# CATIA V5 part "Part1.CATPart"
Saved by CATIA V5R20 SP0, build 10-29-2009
Part number: Part1
Material "Orange"
Material "Stone wall"
Material "Toon"
Material "Aluminium brushed"
Material "Toon"
Material "Satin light red": density 7190 kg/m3, Young's modulus 7e+10 Pa, Poisson ratio 0.3, thermal expansion 6.2e-06 1/K
Bounding box of the stored display mesh (mm): x -357.963 to 357.963, y -357.963 to 357.963, z -36 to 695.353
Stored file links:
  D:\liandongzhou\Part1.CATPart
  D:\catiaM\win_b64\startup\materials\Advanced_Materials.CATMaterial
  D:\catiaM\win_b64\startup\materials\shaders\CATIA_Toon.cgfx
  D:\catiaM\win_b64\startup\materials\shaders\CATIA_Diffuse_2DMap_StoneWall_256.dds
  D:\catiaM\win_b64\startup\materials\shaders\CATIA_Normal_2DMap_StoneWall_512.dds
  D:\catiaM\win_b64\startup\materials\shaders\CATIA_Leather.cgfx
  D:\catiaM\win_b64\startup\materials\shaders\CATIA_Environment_CUBEMap_Street_1024.dds
  D:\catiaM\win_b64\startup\materials\shaders\CATIA_Normal_2DMap_Flake_1024.dds
  D:\catiaM\win_b64\startup\materials\shaders\CATIA_CarPaint_Polished.cgfx
  D:\catiaM\win_b64\startup\materials\shaders\CATIA_Environment_2DMap_Street_2048.dds
  D:\catiaM\win_b64\startup\materials\shaders\CATIA_Normal_2DMap_Scratches_1024.dds
  D:\catiaM\win_b64\startup\materials\shaders\CATIA_Metal_Brushed.cgfx
  D:\catiaM\win_b64\startup\materials\shaders\CATIA_Diffuse_2DMap_WoodCedar_512.dds
  D:\catiaM\win_b64\startup\materials\shaders\CATIA_Environment_CUBEMap_Hall_1024.dds
  D:\catiaM\win_b64\startup\materials\shaders\CATIA_Wood_Polished.cgfx
  D:\catiaM\win_b64\startup\materials\textures\wire_netting.png
  D:\catiaM\win_b64\startup\materials\environment_map\CATIA_Environment_2DMap_Chroma1_256.jpg
  D:\catiaM\win_b64\startup\materials\environment_map\CATIA_Environment_2DMap_LightRedSatin_256.jpg
  D:\catiaM\win_b64\startup\materials\textures\hex_grid.png
  D:\catiaM\win_b64\startup\materials\environment_map\CATIA_Environment_2DMap_Garden_256.jpg
  D:\liandongzhou\V.CATPart
  D:\catiaM\win_b64\startup\materials\environment_map\CATIA_Environment_2DMap_Chroma2_256.jpg
  D:\catiaM\win_b64\startup\materials\environment_map\CATIA_Environment_2DMap_DarkRedSatin_256.jpg
  D:\catiaM\win_b64\startup\materials\shaders\CATIA_Normal_2DMap_GridPlate_1024.dds
  D:\catiaM\win_b64\startup\materials\shaders\CATIA_Environment_2DMap_Hall_2048.dds
  D:\catiaM\win_b64\startup\materials\shaders\CATIA_Normal_2DMap_MZDotGrid_1024.dds
  D:\catiaM\win_b64\startup\materials\shaders\CATIA_Opacity_2DMap_MZDotGrid_1024.dds
  D:\catiaM\win_b64\startup\materials\shaders\CATIA_Metal_Grid.cgfx
  D:\catiaM\win_b64\startup\materials\environment_map\CATIA_Environment_2DMap_Satin_256.jpg
  D:\catiaM\win_b64\startup\materials\textures\dot_grid.png
  D:\catiaM\win_b64\startup\materials\textures\dot_grid2.png
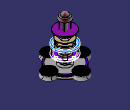
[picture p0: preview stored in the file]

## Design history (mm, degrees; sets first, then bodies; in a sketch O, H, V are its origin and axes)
Set1
  Plane1: type Offset, RefPlane xy-plane, Offset 10
  Set2
    Plane2: type Offset, RefPlane xy-plane, Offset 20 {= Plane1.Offset * 2}
    Plane3: type Offset, RefPlane xy-plane, Offset 30 {= Plane1.Offset * 3}
    Plane4: type Offset, RefPlane xy-plane, Offset 40 {= Plane1.Offset * 4}
    Plane5: type Offset, RefPlane xy-plane, Offset 50 {= Plane1.Offset * 5}
    Plane6: type Offset, RefPlane xy-plane, Offset 60 {= Plane1.Offset * 6}
    Plane7: type Offset, RefPlane xy-plane, Offset 70 {= Plane1.Offset * 7}
    Plane8: type Offset, RefPlane xy-plane, Offset 80 {= Plane1.Offset * 8}
    Plane9: type Offset, RefPlane xy-plane, Offset 90 {= Plane1.Offset * 9}
    Plane10: type Offset, RefPlane xy-plane, Offset 100 {= Plane1.Offset * 10}
    Plane11: type Offset, RefPlane xy-plane, Offset 110 {= Plane1.Offset * 11}
    Plane12: type Offset, RefPlane xy-plane, Offset 120 {= Plane1.Offset * 12}
    Plane13: type Offset, RefPlane xy-plane, Offset 130 {= Plane1.Offset * 13}
    Plane14: type Offset, RefPlane xy-plane, Offset 140 {= Plane1.Offset * 14}
    Plane15: type Offset, RefPlane xy-plane, Offset 150 {= Plane1.Offset * 15}
    Plane16: type Offset, RefPlane xy-plane, Offset 160 {= Plane1.Offset * 16}
    Plane17: type Offset, RefPlane xy-plane, Offset 170 {= Plane1.Offset * 17}
    Plane18: type Offset, RefPlane xy-plane, Offset 180 {= Plane1.Offset * 18}
    Plane19: type Offset, RefPlane xy-plane, Offset 190 {= Plane1.Offset * 19}
    Plane20: type Offset, RefPlane xy-plane, Offset 200 {= Plane1.Offset * 20}
    Plane21: type Offset, RefPlane xy-plane, Offset 210 {= Plane1.Offset * 21}
    Plane22: type Offset, RefPlane xy-plane, Offset 220 {= Plane1.Offset * 22}
    Plane23: type Offset, RefPlane xy-plane, Offset 230 {= Plane1.Offset * 23}
    Plane24: type Offset, RefPlane xy-plane, Offset 240 {= Plane1.Offset * 24}
    Plane25: type Offset, RefPlane xy-plane, Offset 250 {= Plane1.Offset * 25}
    Plane26: type Offset, RefPlane xy-plane, Offset 260 {= Plane1.Offset * 26}
  Plane27: type Offset, RefPlane xy-plane, Offset 30, reversed
  Sketch1 on Plane27, origin (0, 0, -30), H (1, 0, 0), V (0, 1, 0)
    circle A1 centre (0, 0) radius 250
    radius A1 = 250
    radius A1 = 250 (reference)
Body1 (main body), material "Stone wall"
  Pad1: profile Sketch1, direction (0, 0, -1), length 6
  Sketch2 on xy-plane, origin (0, 0, 0), H (1, 0, 0), V (0, 1, 0)
    circle A1 centre (0, 0) radius 250
    radius A1 = 250
  Pad2: profile Sketch2, direction (0, 0, 1), length 10
  Sketch3 on end face of Pad1, origin (0, 0, -36), H (1, 0, 0), V (0, -1, 0)
    point P1 (125, 0)
    reference projected circle E1 centre (0, 0) radius 250 from Sketch2.A1
    point P2 (250, 0)
    circle A1 centre (250, 0) radius 100
    circle A2 centre (250, 0) radius 110
    distance P1 O = 125
    radius E1 = 250 (reference)
    radius A1 = 100
    distance V P2 = 250
    radius A2 = 110
    coincidence: P1 H, P2 H
  Line1: type PtDir, RefPoint Sketch3.P1, Direction (0, 0, 1), Start 0, End 20
  Plane28: type Normal, Curve Line1, RefPoint Sketch3.P1
  Plane29: type Offset, RefPlane Plane28, Offset 5
  Set3
    Plane30: type Offset, RefPlane Plane28, Offset 10 {= Plane29.Offset * 2}
    Plane31: type Offset, RefPlane Plane28, Offset 15 {= Plane29.Offset * 3}
    Plane32: type Offset, RefPlane Plane28, Offset 20 {= Plane29.Offset * 4}
    Plane33: type Offset, RefPlane Plane28, Offset 25 {= Plane29.Offset * 5}
    Plane34: type Offset, RefPlane Plane28, Offset 30 {= Plane29.Offset * 6}
    Plane35: type Offset, RefPlane Plane28, Offset 35 {= Plane29.Offset * 7}
    Plane36: type Offset, RefPlane Plane28, Offset 40 {= Plane29.Offset * 8}
    Plane37: type Offset, RefPlane Plane28, Offset 45 {= Plane29.Offset * 9}
    Plane38: type Offset, RefPlane Plane28, Offset 50 {= Plane29.Offset * 10}
    Plane39: type Offset, RefPlane Plane28, Offset 55 {= Plane29.Offset * 11}
  Sketch4 on Plane31, origin (0, 0, -21), H (1, 0, 0), V (0, 1, 0)
    circle A1 centre (125, 0) radius 2.8352
    point P1 (125, 0)
    point P2 (127.8352, 0)
    distance P1 V = 125
    coincidence: P1 H, A1 P2, P2 H
  Sketch5 on Plane35, origin (0, 0, -1), H (1, 0, 0), V (0, 1, 0)
    point P1 (125, 0)
    circle A1 centre (250, 0) radius 83
    point P2 (250, 0)
    distance V P2 = 250
    radius A1 = 83
    coincidence: P2 H
  Sketch6 on Plane36, origin (0, 0, 4), H (1, 0, 0), V (0, 1, 0)
    point P1 (125, 0)
    circle A1 centre (250, 0) radius 88
    point P2 (250, 0)
    radius A1 = 88
    distance V P2 = 250
    coincidence: P2 H
  Sketch7 on Plane37, origin (0, 0, 9), H (1, 0, 0), V (0, 1, 0)
    point P1 (125, 0)
    circle A1 centre (249.5227, 0) radius 93
    point P2 (249.5227, 0)
    distance P1 H = 0
    radius A1 = 93
    coincidence: P2 H
  Sketch8 on Plane38, origin (0, 0, 14), H (1, 0, 0), V (0, 1, 0)
    point P1 (125, 0)
    circle A1 centre (250, 0) radius 98
    reference projected circle E1 centre (0, 0) radius 250 from Sketch2.A1
    distance P1 H = 0
    distance P1 V = 125
    radius A1 = 98
    radius E1 = 250 (reference)
  Sketch9 on Plane39, origin (0, 0, 19), H (1, 0, 0), V (0, 1, 0)
    point P1 (125, 0)
    circle A1 centre (250, 0) radius 106.5
    point P2 (250, 0)
    distance P1 H = 0
    distance P1 V = 125
    radius A1 = 106.5
    coincidence: P2 H
  Plane40: type Offset, RefPlane Plane39, Offset 5
  Set4
    Plane41: type Offset, RefPlane Plane39, Offset 10 {= Plane40.Offset * 2}
    Plane42: type Offset, RefPlane Plane39, Offset 15 {= Plane40.Offset * 3}
    Plane43: type Offset, RefPlane Plane39, Offset 20 {= Plane40.Offset * 4}
  Sketch10 on xy-plane, origin (0, 0, 0), H (1, 0, 0), V (0, 1, 0)
    circle A1 centre (0, 0) radius 40
    point P1 (0, 0)
    distance P1 H = 0
    distance P1 V = 0
    radius A1 = 40
  Sketch11 on Plane27, origin (0, 0, -30), H (1, 0, 0), V (0, 1, 0)
    circle A1 centre (0, 0) radius 40
    point P1 (0, 0)
    distance P1 H = 0
    distance P1 V = 0
    radius A1 = 40
  Body2 "底座凹槽"
    Loft1: solid, Sections (Sketch11; Sketch10)
  Trim1: tool Body2
  Sketch12 on Plane2, origin (0, 0, 20), H (1, 0, 0), V (0, 1, 0)
    circle A1 centre (0, 0) radius 70
    radius A1 = 70
  Pad3 "紫二层": profile Sketch12, direction (0, 0, 1), length 17, mirrored extent
  Sketch13 on start face of Pad3, origin (0, 0, 3), H (1, 0, 0), V (0, -1, 0)
    circle A1 centre (0, 0) radius 70
    arc A2 centre (48.9898, -50) radius 12 from (39.7301, -57.6326) to (56.8098, -40.898) ccw
    point P1 (48.9898, -50)
    arc A3 centre (-48.9898, 50) radius 12 from (-39.7301, 57.6326) to (-56.8098, 40.898) ccw
    point P2 (-48.9898, 50)
    construction line L1 (48.9898, -50) -> (30, -70)
    construction line L2 (48.9898, -50) -> (80, -19.6163)
    point P5 (56.8098, -40.898)
    point P6 (39.7301, -57.6326)
    axis line L3 (-30, 70) -> (-68.0952, 30)
    point P9 (-56.8098, 40.898)
    point P10 (-39.7301, 57.6326)
    radius A1 = 70
    radius A3 = 12
    radius A2 = 12
    coincidence: P1 A1, P2 A1, A1 P5, A1 P6, A1 P9, A1 P10
    tangency: L2 A1, L3 A1
  Body3 "pulley"
    Sketch14 on Plane44, origin (0, 0, 0), H (0, 1, 0), V (0, 0, 1)
      construction line L1 (0, 33) -> (180, 33)
      reference projected line E1 (-70, 37) -> (70, 37) from edge [face of Pad3 from Sketch12.A1 | end face of Pad3]
      distance L1 E1 = 4
      horizontal: L1 H
    Sketch15 on Plane44, origin (0, 0, 0), H (0, 1, 0), V (0, 0, 1)
      construction line L1 (0, 21) -> (180, 21)
      point P1 (0, 21)
      construction line L2 (65.5, 50) -> (65.5, -20)
      construction line L3 (40.5, 40) -> (40.5, -30)
      construction line L4 (0, 36) -> (78.6177, 36)
      point P7 (0, 36)
      construction line L5 (0, 18) -> (84.1873, 18)
      point P9 (0, 18)
      reference projected line E1 (-70, 3) -> (70, 3) from edge [start face of Pad3 | face of Pad3 from Sketch12.A1]
      construction line L6 (-159.9768, 21) -> (244.4965, 36)
      point P11 (-159.9768, 21)
      point P12 (244.4965, 36)
      construction line L7 (-159.9768, 21) -> (-123.6891, 18)
      point P13 (-123.6891, 18)
      line L8 (40.5, 28.4347) -> (40.5, 4.4261)
      point P14 (40.5, 28.4347)
      point P15 (40.5, 4.4261)
      line L9 (40.5, 28.4347) -> (96.2575, 30.5025)
      line L10 (40.5, 4.4261) -> (96.2575, -0.1835)
      line L11 (96.2575, 30.5025) -> (96.2575, -0.1835)
      distance L2 V = 65.5
      distance L3 L2 = 25
      distance L4 L1 = 15
      distance L5 E1 = 15
      angle L6 L7 = 6.8499
      coincidence: P1 V, P7 V, P9 V, P11 L1, P12 L4, P13 L5, P14 L6, P14 L3, P15 L7
      horizontal: L1 H, L4 H, L5 H
      vertical: L2 V, L3 V, L8 V, L11 V
      parallelism: L9 L6, L10 L7
    Shaft1: profile Sketch15, axis Sketch15.V, angle 360
  Remove1: tool Body3
Body4
  Line2: type PtDir, RefPoint Sketch12.O, Direction (0, 0, 1), Start 0, End 20
  Plane44: type 2Lines, Element1 Sketch12.V, Element2 Line2
Body5, material "Orange"
  Sketch16 on Plane5, origin (0, 0, 50), H (1, 0, 0), V (0, 1, 0)
    circle A1 centre (0, 0) radius 32.861
  Pad4: profile Sketch16, direction (0, 0, -1), length 30
Body6, material "Toon"
  Sketch17 on Plane5, origin (0, 0, 50), H (1, 0, 0), V (0, 1, 0)
    circle A1 centre (0, 0) radius 70.6625
  Pad5: profile Sketch17, direction (0, 0, 1), length 6
  Sketch18 on Plane7, origin (0, 0, 70), H (1, 0, 0), V (0, 1, 0)
    circle A1 centre (0, 0) radius 79.2104
  Pad6: profile Sketch18, direction (0, 0, -1), length 4
  Fillet1: radius 4, on edge [end face of Pad6 | face of Pad6 from Sketch18.A1]
  Sketch19 on end face of Pad5, origin (0, 0, 56), H (1, 0, 0), V (0, 1, 0)
    circle A1 centre (0, 0) radius 28.2843
  Pad7: profile Sketch19, direction (0, 0, 1), length 12
  Fillet2: radius 3, on edge [face of Pad5 from Sketch17.A1 | end face of Pad5]; edge [start face of Pad5 | face of Pad5 from Sketch17.A1]
  Sketch20 on start face of Pad6, origin (0, 0, 70), H (1, 0, 0), V (0, 1, 0)
    arc A1 centre (0, 0) radius 63.2456 from (-20, 60) to (-60.2299, 19.2965) ccw
    arc A2 centre (0, 0) radius 30 from (-10, 28.2843) to (-27.0282, 13.0183) ccw
    line L1 (-20, 60) -> (-10, 28.2843)
    line L2 (10, 28.2843) -> (20, 60)
    line L3 (-27.0282, 13.0183) -> (-60.2299, 19.2965)
    line L4 (-27.0282, -13.0183) -> (-59.658, -20.9982)
    point P7 (-27.0282, -13.0183)
    line L5 (-12.7179, -27.1709) -> (-21.2168, -59.5806)
    point P8 (-12.7179, -27.1709)
    point P9 (-21.2168, -59.5806)
    point P10 (26.5846, -13.9017)
    line L6 (12.7179, -27.1709) -> (20.6893, -59.7658)
    point P11 (12.7179, -27.1709)
    point P12 (20.6893, -59.7658)
    arc A3 centre (0, 0) radius 30 from (-27.0282, -13.0183) to (-12.7179, -27.1709) ccw
    arc A4 centre (0, 0) radius 30 from (12.7179, -27.1709) to (26.5846, -13.9017) ccw
    arc A5 centre (0, 0) radius 30 from (26.5846, 13.9017) to (10, 28.2843) ccw
    arc A6 centre (0, 0) radius 63.2456 from (60.2299, 19.2965) to (20, 60) ccw
    arc A7 centre (0, 0) radius 63.2456 from (-59.658, -20.9982) to (-21.2168, -59.5806) ccw
    arc A8 centre (0, 0) radius 63.2456 from (20.6893, -59.7658) to (59.9305, -20.2073) ccw
    line L7 (26.5846, 13.9017) -> (60.2299, 19.2965)
    line L8 (26.5846, -13.9017) -> (59.9305, -20.2073)
    point P16 (26.5846, -13.9017)
    coincidence: P7 A2, P8 A2, P9 A1, P10 A2, P11 A2, P12 A1, A2 A3, A3 A4, A4 A5, A1 A6, A1 A7, A7 A8, P16 A4
    perpendicularity: L6 L4
    parallelism: L8 L3
  Pocket1: profile Sketch20, direction (0, 0, -1), length 3
Body7 "螺纹柱"
  Sketch21 on start face of Pad6, origin (0, 0, 70), H (1, 0, 0), V (0, 1, 0)
    circle A1 centre (0, -50) radius 10
    point P1 (0, -50)
    radius A1 = 10
    coincidence: P1 V
  Pad8: profile Sketch21, direction (0, 0, 1), length 65
  Sketch22 on end face of Pad8, origin (0, 0, 135), H (1, 0, 0), V (0, 1, 0)
    point P1 (0, -50)
    coincidence: P1 V
  Line3: type PtDir, RefPoint Sketch22, Direction (0, 0, 1), Start 0, End 65
  Sketch23 on end face of Pad8, origin (0, 0, 135), H (1, 0, 0), V (0, 1, 0)
    circle A1 centre (0, -50) radius 7.5
    radius A1 = 7.5
  Pocket2: profile Sketch23, direction (0, 0, -1), length 65
  Body8
    Line4: type PtDir, RefPoint Sketch22, Direction (0, 0, 1), Start 0, End 65
    Point1: type OnSurface, Support face of Pad8 from Sketch21.A1, Length 26.383, Direction (0.0172, 0.0004, 0.9999)
    Helix1: Direction Line4, RefPoint Point1, Pitch 5, Height 50, TaperAngle 0
    Line5: type PtDir, RefPoint Point1, Direction (0, 1, 0), Start 0, End 5
    Point2: type OnCurve, Support Helix1, Length 626.365
    Connect1: Curve1 Line5, Point1 vertex of Line5, Tension1 1, Curve2 Helix1, Point2 Point2, Tension2 1
    Plane45: type Normal, Curve Connect1, RefPoint vertex of Connect1
    Line6: type PtDir, RefPoint vertex of Helix1, Direction (0, 1, 0), Start 0, End 5
    Point3: type OnCurve, Support Connect1, Length 5.538
    Connect2: Curve1 Line6, Point1 vertex of Line6, Tension1 1, Curve2 Connect1, Point2 Point3, Tension2 1
    Circle1: type CtrRad, Start 0, End 180, Center vertex of Connect1, Support Plane45, Radius 1.5, FirstDirection (-1, 0, 0)
    Rib1: profile Circle1, centre curve Connect2
    Body9
      Sketch24 on end face of Pad8, origin (0, 0, 135), H (1, 0, 0), V (0, 1, 0)
        circle A1 centre (0, -50) radius 7.5
        point P1 (0, -50)
        radius A1 = 7.5
        coincidence: P1 V
      Pad9: profile Sketch24, direction (0, 0, -1), length 65
    Remove2: tool Body9
  Assemble1: tool Body8
  CircPattern1: of the body so far, instances 4, angular step 90, axis from face of Fillet1
  Sketch25 on Plane14, origin (0, 0, 140), H (1, 0, 0), V (0, 1, 0)
    circle A1 centre (0, 0) radius 164.9242
    radius A1 = 164.9242
  Pad10: profile Sketch25, direction (0, 0, 1), length 5, mirrored extent
  Sketch26 on end face of Pad10, origin (0, 0, 145), H (1, 0, 0), V (0, 1, 0)
    circle A1 centre (0, 0) radius 143.1782
    circle A2 centre (0, 0) radius 123.6932
  Pocket3: profile Sketch26, direction (0, 0, -1), length 10
  Sketch27 on end face of Pad10, origin (0, 0, 145), H (1, 0, 0), V (0, 1, 0)
    line L1 (110.2028, 4.471) -> (143.5222, 22.8974)
    point P2 (143.5222, 22.8974)
    line L2 (110.2028, -5.0712) -> (143.5222, -23.1686)
    point P4 (143.5222, -23.1686)
    connectcurve C1
    spline S1 through (147.1511, 22.8974) (157.7077, 9.0776) (158.9895, -5.0712) (147.1511, -25.1396)
    spline S2 through (143.5222, 22.8974) (147.1511, 22.8974) (190.6972, -9.0197)
    spline S3 through (143.5222, -23.1686) (147.1511, -25.1396) (211.8105, 32.1106)
    point P5 (147.1511, 22.8974)
    point P6 (147.1511, -25.1396)
    point P7 (147.1511, -25.1396)
    point P8 (147.1511, 22.8974)
    point P9 (147.1511, 22.8974)
    point P10 (143.5222, -23.1686)
    point P11 (147.1511, -25.1396)
    point P12 (143.5222, 22.8974)
    coincidence: P7 L2, P8 P9, P10 P4, P11 P7, P9 P5, P7 P6, P2 P12
Body10
  Pad11: profile Sketch27, direction (0, 0, -1), length 7, mirrored extent
  CircPattern2: of Pad11, instances 4, angular step 90, axis from end face of Pad10
  Fillet3: radius 4, on face of CircPattern2 (x3); start face of Pad11
  Sketch28 on Plane15, origin (0, 0, 150), H (1, 0, 0), V (0, 1, 0)
    circle A1 centre (0, 0) radius 81.3761
Body11, material "Aluminium brushed"
  Pad12: profile Sketch28, direction (0, 0, 1), length 8, mirrored extent
  Fillet4: radius 15, on end face of Pad12
  Sketch29 on end face of Pad12, origin (0, 0, 158), H (1, 0, 0), V (0, 1, 0)
    circle A1 centre (0, 0) radius 47.5
    radius A1 = 47.5
  Pad13: profile Sketch29, direction (0, 0, 1), length 100
  Plane46: type Offset, RefPlane Plane26, Offset 35
  Sketch30 on end face of Pad12, origin (0, 0, 158), H (1, 0, 0), V (0, 1, 0)
    circle A1 centre (0, 0) radius 47.5
    circle A2 centre (0, 0) radius 55
    radius A2 = 55
    radius A1 = 47.5
  Sketch31 on end face of Pad12, origin (0, 0, 158), H (1, 0, 0), V (0, 1, 0)
    reference projected circle E1 centre (0, 0) radius 47.5 from Sketch30.A1
    radius E1 = 47.5 (reference)
  Pocket4: profile Sketch30, direction (0, 0, -1), length 6
Body12
  DatumCurve1
  Sketch32 on end face of Pad13, origin (0, 0, 258), H (1, 0, 0), V (0, 1, 0)
    reference projected circle E1 centre (0, 0) radius 98.7386 from edge of DatumCurve1
    circle A1 centre (0, 0) radius 98.7385
    circle A2 centre (0, 0) radius 164.924
    radius E1 = 98.7386 (reference)
    radius A1 = 98.7385
    radius A2 = 164.924
  Pad14: profile Sketch32, direction (0, 0, 1), length 25
  Sketch33 on end face of Pad14, origin (0, 0, 283), H (1, 0, 0), V (0, 1, 0)
    circle A1 centre (0, 0) radius 128.1586
  Pocket5: profile Sketch33, direction (0, 0, -1), length 20
  Fillet5: radius 13, on edge [end face of Pad14 | face of Pocket5 from Sketch33.A1]
  Sketch34 on end face of Pad10, origin (0, 0, 145), H (1, 0, 0), V (0, 1, 0)
    ellipse A1 centre (116.9782, -87.953) semi-axes 22.2524, 13.0183 rotation 42.881
    ellipse A2 centre (-126.4866, 76.3677) semi-axes 23.4298, 11.1664 rotation 225.897
Body13, material "无"
  Pad15: profile Sketch34, direction (0, 0, 1), length 114
  Sketch35 on end face of Pad14, origin (0, 0, 283), H (1, 0, 0), V (0, 1, 0)
    circle A1 centre (-150.3688, 0) radius 9.6261
    point P1 (-150.3688, 0)
    coincidence: P1 H
  Plane47: type 1Curve, Element1 Sketch35
  Plane48: type Offset, RefPlane Plane47, Offset 35
  Set5
    Plane49: type Offset, RefPlane Plane47, Offset 70 {= Plane48.Offset * 2}
    Plane50: type Offset, RefPlane Plane47, Offset 105 {= Plane48.Offset * 3}
    Plane51: type Offset, RefPlane Plane47, Offset 140 {= Plane48.Offset * 4}
    Plane52: type Offset, RefPlane Plane47, Offset 175 {= Plane48.Offset * 5}
  Sketch36 on Plane47, origin (0, 0, 283), H (1, 0, 0), V (0, 1, 0)
    circle A1 centre (-150, 0) radius 10
    point P1 (-150, 0)
    coincidence: P1 H
  Sketch37 on Plane48, origin (0, 0, 318), H (1, 0, 0), V (0, 1, 0)
    circle A1 centre (-150, 0) radius 6.0874
    point P1 (-150, 0)
    point P2 (-143.9126, 0)
    coincidence: P1 H, A1 P2, P2 H
  Sketch38 on Plane49, origin (0, 0, 353), H (1, 0, 0), V (0, 1, 0)
    circle A1 centre (-150, 0) radius 3.9423
    point P1 (-150, 0)
    coincidence: P1 H
  Sketch39 on Plane50, origin (0, 0, 388), H (1, 0, 0), V (0, 1, 0)
    circle A1 centre (-150, 0) radius 1
    point P1 (-150, 0)
    radius A1 = 1
    coincidence: P1 H
Body14, material "无"
  Loft2: solid, Sections (Sketch36; Sketch37; Sketch38; Sketch39)
  CircPattern3: of Loft2, instances 2, angular step 180, axis from end face of Pad14
  Sketch40 on end face of Pad10, origin (0, 0, 145), H (1, 0, 0), V (0, 1, 0)
    ellipse A1 centre (-93.5316, -118.6091) semi-axes 22.2121, 9.5133 rotation 322.771
    ellipse A2 centre (107.3212, 110.0776) semi-axes 26.2508, 10.7441 rotation 134.291
  Pad16: profile Sketch40, direction (0, 0, 1), length 114
  Sketch41 on end face of Pocket5, origin (0, 0, 263), H (1, 0, 0), V (0, 1, 0)
    circle A1 centre (0, 0) radius 117.1393
Body15
Body16
  Sketch42 on end face of Pocket5, origin (0, 0, 263), H (1, 0, 0), V (0, 1, 0)
    circle A1 centre (0, 0) radius 114.765
  Pad17: profile Sketch42, direction (0, 0, 1), length 35
  Sketch43 on end face of Pad17, origin (0, 0, 298), H (1, 0, 0), V (0, 1, 0)
    circle A1 centre (0, 0) radius 98.7385
    radius A1 = 98.7385
  Pocket6: profile Sketch43, direction (0, 0, -1), length 35
  Sketch44 on end face of Pad17, origin (0, 0, 298), H (1, 0, 0), V (0, 1, 0)
    line L1 (102.1641, 7.5708) -> (102.1641, -7.5708)
    line L2 (102.1641, -7.5708) -> (5.6547, -7.5708)
    line L3 (-102.1641, -7.5708) -> (-102.1641, 7.5708)
    line L4 (-102.1641, 7.5708) -> (-5.6547, 7.5708)
    line L5 (5.6547, 102.7272) -> (5.6547, 7.5708)
    line L6 (5.6547, -102.7272) -> (-5.6547, -102.7272)
    line L7 (-5.6547, -102.7272) -> (-5.6547, -7.5708)
    line L8 (-5.6547, 102.7272) -> (5.6547, 102.7272)
    point P9 (5.6547, 7.5708)
    line L9 (5.6547, -7.5708) -> (5.6547, -102.7272)
    point P11 (-5.6547, -7.5708)
    line L10 (-5.6547, 7.5708) -> (-5.6547, 102.7272)
    line L11 (-5.6547, -7.5708) -> (-102.1641, -7.5708)
    line L12 (5.6547, 7.5708) -> (102.1641, 7.5708)
    vertical: L1 V, L3 V, L5 V, L7 V, L9 V, L10 V
    horizontal: L2 H, L4 H, L6 H, L8 H, L11 H, L12 H
    equidistance: L1 L3 O, L2 L4 O, L5 L7 O, L6 L8 O
    coincidence: L4 P9, L5 L9, L2 P11, L7 L10, L2 L11, L4 L12
  Sketch45 on end face of Pad17, origin (0, 0, 298), H (1, 0, 0), V (0, 1, 0)
    point P1 (106.4577, 0)
    line L1 (117.701, 9.5493) -> (117.701, -9.5493)
    line L2 (117.701, -9.5493) -> (95.2144, -9.5493)
    line L3 (95.2144, -9.5493) -> (95.2144, 9.5493)
    line L4 (95.2144, 9.5493) -> (117.701, 9.5493)
    point P6 (-106.1431, 0)
    line L5 (-94.2184, 9.5493) -> (-94.2184, -9.5493)
    line L6 (-94.2184, -9.5493) -> (-118.0679, -9.5493)
    line L7 (-118.0679, -9.5493) -> (-118.0679, 9.5493)
    line L8 (-118.0679, 9.5493) -> (-94.2184, 9.5493)
    point P8 (-94.2184, -9.5493)
    coincidence: P1 H, P6 H, P8 L2
    vertical: L1 V, L3 V, L5 V, L7 V
    horizontal: L2 H, L4 H, L6 H, L8 H
    equidistance: L1 L3 P1, L2 L4 P1, L5 L7 P6, L6 L8 P6
  Pocket7: profile Sketch45, direction (0, 0, -1), length 13
  Sketch46 on end face of Pad17, origin (0, 0, 298), H (1, 0, 0), V (0, 1, 0)
    point P1 (0, -106.356)
    line L1 (10, -95.674) -> (10, -117.0379)
    line L2 (10, -117.0379) -> (-10, -117.0379)
    line L3 (-10, -117.0379) -> (-10, -95.674)
    line L4 (-10, -95.674) -> (10, -95.674)
    point P6 (0, 106.3118)
    line L5 (10, 116.3464) -> (10, 96.2773)
    line L6 (10, 96.2773) -> (-10, 96.2773)
    line L7 (-10, 96.2773) -> (-10, 116.3464)
    line L8 (-10, 116.3464) -> (10, 116.3464)
    length L4 = 20
    coincidence: P1 V, P6 V
    vertical: L1 V, L3 V, L5 V, L7 V
    horizontal: L2 H, L4 H, L6 H, L8 H
    equidistance: L1 L3 P1, L2 L4 P1, L5 L7 P6, L6 L8 P6
  Pocket8: profile Sketch46, direction (0, 0, -1), length 13
Body17
  Sketch47 on end face of Pad17, origin (0, 0, 298), H (1, 0, 0), V (0, 1, 0)
    line L1 (99.3326, 11.8373) -> (99.3326, -11.8373)
    line L2 (99.3326, -11.8373) -> (12.9134, -11.8373)
    line L3 (-99.3326, -11.8373) -> (-99.3326, 11.8373)
    line L4 (-99.3326, 11.8373) -> (-12.9134, 11.8373)
    line L5 (12.9134, 100.3374) -> (12.9134, 11.8373)
    line L6 (12.9134, -100.3374) -> (-12.9134, -100.3374)
    line L7 (-12.9134, -100.3374) -> (-12.9134, -11.8373)
    line L8 (-12.9134, 100.3374) -> (12.9134, 100.3374)
    point P9 (-12.9134, 11.8373)
    line L9 (12.9134, 11.8373) -> (99.3326, 11.8373)
    point P11 (12.9134, -11.8373)
    line L10 (-12.9134, -11.8373) -> (-99.3326, -11.8373)
    line L11 (-12.9134, 11.8373) -> (-12.9134, 100.3374)
    line L12 (12.9134, -11.8373) -> (12.9134, -100.3374)
    length L1 = 23.6746
    vertical: L1 V, L3 V, L5 V, L7 V, L11 V, L12 V
    horizontal: L2 H, L4 H, L6 H, L8 H, L9 H, L10 H
    equidistance: L1 L3 O, L2 L4 O, L5 L7 O, L6 L8 O
    coincidence: L7 P9, L4 L9, L5 P11, L2 L10, L7 L11, L5 L12
  Pad18: profile Sketch47, direction (0, 0, -1), length 13
  Shell1: IntOffset 2, Face (face of Pad18 from Sketch47.L6; face of Pad18 from Sketch47.L8; face of Pad18 from Sketch47.L1; face of Pad18 from Sketch47.L3), ExtOffset 0
  Plane53: type Offset, RefPlane start face of Pad18, Offset 0, reversed
  Plane54: type Offset, RefPlane Plane53, Offset 10, reversed
  Set6
    Plane55: type Offset, RefPlane Plane53, Offset 20 {= Plane54.Offset * 2}, reversed
    Plane56: type Offset, RefPlane Plane53, Offset 30 {= Plane54.Offset * 3}, reversed
    Plane57: type Offset, RefPlane Plane53, Offset 40 {= Plane54.Offset * 4}, reversed
    Plane58: type Offset, RefPlane Plane53, Offset 50 {= Plane54.Offset * 5}, reversed
    Plane59: type Offset, RefPlane Plane53, Offset 60 {= Plane54.Offset * 6}, reversed
  Sketch48 on Plane53, origin (0, 0, 298), H (1, 0, 0), V (0, -1, 0)
    circle A1 centre (0, 0) radius 60
    radius A1 = 60
  Sketch49 on Plane58, origin (0, 0, 348), H (1, 0, 0), V (0, -1, 0)
    circle A1 centre (0, 0) radius 65
    radius A1 = 65
  Sketch50 on Plane57, origin (0, 0, 338), H (1, 0, 0), V (0, -1, 0)
    circle A1 centre (0, 0) radius 60
    radius A1 = 60
  Sketch51 on Plane56, origin (0, 0, 328), H (1, 0, 0), V (0, -1, 0)
    circle A1 centre (0, 0) radius 55
    radius A1 = 55
  Sketch52 on Plane55, origin (0, 0, 318), H (1, 0, 0), V (0, -1, 0)
    circle A1 centre (0, 0) radius 50
    radius A1 = 50
  Sketch53 on Plane54, origin (0, 0, 308), H (1, 0, 0), V (0, -1, 0)
    circle A1 centre (0, 0) radius 45
    radius A1 = 45
Body18
Body19, material "Toon"
  Sketch54 on Plane34, origin (0, 0, -6), H (1, 0, 0), V (0, 1, 0)
    circle A1 centre (250, 0) radius 83
    point P1 (250, 0)
    radius A1 = 83
    coincidence: P1 H
  Sketch55 on Plane33, origin (0, 0, -11), H (1, 0, 0), V (0, 1, 0)
    circle A1 centre (250, 0) radius 88
    point P1 (250, 0)
    radius A1 = 88
    coincidence: P1 H
  Sketch56 on Plane32, origin (0, 0, -16), H (1, 0, 0), V (0, 1, 0)
    circle A1 centre (250, 0) radius 93
    point P1 (250, 0)
    radius A1 = 93
    coincidence: P1 H
  Sketch57 on Plane31, origin (0, 0, -21), H (1, 0, 0), V (0, 1, 0)
    circle A1 centre (250, 0) radius 98
    point P1 (250, 0)
    radius A1 = 98
    coincidence: P1 H
  Sketch58 on Plane30, origin (0, 0, -26), H (1, 0, 0), V (0, 1, 0)
    circle A1 centre (250, 0) radius 103
    point P1 (250, 0)
    radius A1 = 103
    coincidence: P1 H
  Plane60: type Offset, RefPlane Plane39, Offset 10
  Set7
    Plane61: type Offset, RefPlane Plane39, Offset 20 {= Plane60.Offset * 2}
    Plane62: type Offset, RefPlane Plane39, Offset 30 {= Plane60.Offset * 3}
    Plane63: type Offset, RefPlane Plane39, Offset 40 {= Plane60.Offset * 4}
    Plane64: type Offset, RefPlane Plane39, Offset 50 {= Plane60.Offset * 5}
    Plane65: type Offset, RefPlane Plane39, Offset 60 {= Plane60.Offset * 6}
  Sketch59 on Plane60, origin (0, 0, 29), H (1, 0, 0), V (0, 1, 0)
    circle A1 centre (250, 0) radius 102.5
    point P1 (250, 0)
    radius A1 = 102.5
    coincidence: P1 H
  Plane66: type Offset, RefPlane Plane39, Offset 5
  Sketch60 on Plane27, origin (0, 0, -30), H (1, 0, 0), V (0, 1, 0)
    circle A1 centre (250, 0) radius 108
    point P1 (250, 0)
    radius A1 = 108
    coincidence: P1 H
  Sketch61 on Plane66, origin (0, 0, 24), H (1, 0, 0), V (0, 1, 0)
    circle A1 centre (249.0888, 0) radius 104.5
    point P1 (249.0888, 0)
    radius A1 = 104.5
    coincidence: P1 H
  Loft3: solid, Sections (Sketch3.A1; Sketch60; Sketch58; Sketch57; Sketch56; Sketch55; Sketch54; Sketch5; Sketch6; Sketch7; Sketch8; Sketch9; Sketch61; Sketch59)
  CircPattern4: of the body so far, instances 4, angular step 90, axis from end face of Pad2
Body20
  Sketch62 on face of Loft3, origin (0, 0, 29), H (1, 0, 0), V (0, 1, 0)
    circle A1 centre (250, 0) radius 98
    point P1 (250, 0)
    radius A1 = 98
    coincidence: P1 H
  Pad19: profile Sketch62, direction (0, 0, 1), length 8
  CircPattern5: of the body so far, instances 4, angular step 90, axis from end face of Pad2
  Sketch63 on end face of Pad2, origin (0, 0, 10), H (1, 0, 0), V (0, 1, 0)
    circle A1 centre (0, 0) radius 250
    circle A2 centre (0, 0) radius 229.696
    radius A1 = 250
Body21
  Pad20: profile Sketch63, direction (0, 0, 1), length 15
Body22
  Loft4: solid, Sections (Sketch53; Sketch48)
  Loft5: solid, Sections (edge [face of Loft4 | face of Loft4]; Sketch52; Sketch51; Sketch50; Sketch49)
  Sketch64 on face of Loft5, origin (0, 0, 348), H (1, 0, 0), V (0, 1, 0)
    circle A1 centre (0, 0) radius 88.8065
  Sketch65 on face of Loft5, origin (0, 0, 348), H (1, 0, 0), V (0, 1, 0)
    circle A1 centre (0, 0) radius 124.1005
  Pad21: profile Sketch65, direction (0, 0, 1), length 10
  Fillet6: radius 4, on edge [start face of Pad21 | face of Pad21 from Sketch65.A1]
  Sketch66 on end face of Pad21, origin (0, 0, 358), H (1, 0, 0), V (0, 1, 0)
    circle A1 centre (0, 0) radius 27.5
    radius A1 = 27.5
Body23
  Pad22: profile Sketch66, direction (0, 0, 1), length 60
  Sketch67 on end face of Pad21, origin (0, 0, 358), H (1, 0, 0), V (0, 1, 0)
    circle A1 centre (0, 0) radius 35
    point P1 (35, 0)
    radius A1 = 35
    coincidence: A1 P1, P1 H
  Pad23: profile Sketch67, direction (0, 0, 1), length 25
  DatumCurve2
  Plane67: type 1Curve, Element1 DatumCurve2
  Plane68: type Offset, RefPlane Plane67, Offset 5
  Set8
    Plane69: type Offset, RefPlane Plane67, Offset 10 {= Plane68.Offset * 2}
    Plane70: type Offset, RefPlane Plane67, Offset 15 {= Plane68.Offset * 3}
    Plane71: type Offset, RefPlane Plane67, Offset 20 {= Plane68.Offset * 4}
    Plane72: type Offset, RefPlane Plane67, Offset 25 {= Plane68.Offset * 5}
    Plane73: type Offset, RefPlane Plane67, Offset 30 {= Plane68.Offset * 6}
  Sketch68 on Plane67, origin (0, 0, 418), H (1, 0, 0), V (0, 1, 0)
    circle A1 centre (0, 0) radius 29.2055
    point P1 (29.2055, 0)
    coincidence: A1 P1, P1 H
  Sketch69 on Plane68, origin (0, 0, 423), H (1, 0, 0), V (0, 1, 0)
    circle A1 centre (0, 0) radius 37.2053
  Sketch70 on Plane69, origin (0, 0, 428), H (1, 0, 0), V (0, 1, 0)
    circle A1 centre (0, 0) radius 46.3355
  Sketch71 on Plane70, origin (0, 0, 433), H (1, 0, 0), V (0, 1, 0)
    circle A1 centre (0, 0) radius 60.7781
  Sketch72 on Plane71, origin (0, 0, 438), H (1, 0, 0), V (0, 1, 0)
    circle A1 centre (0, 0) radius 76.5778
Body24
  Loft6: solid, Sections (Sketch72; Sketch71; Sketch70; Sketch69; Sketch68)
  Sketch73 on Plane71, origin (0, 0, 438), H (1, 0, 0), V (0, 1, 0)
    circle A1 centre (0, 0) radius 146.9733
Body25
  Pad24: profile Sketch73, direction (0, 0, 1), length 13
  Sketch74 on end face of Pad24, origin (0, 0, 451), H (1, 0, 0), V (0, 1, 0)
    circle A1 centre (0, 0) radius 146.9733
  Sketch75 on end face of Pad24, origin (0, 0, 451), H (1, 0, 0), V (0, 1, 0)
    circle A1 centre (0, 0) radius 146.9733
  Sketch76 on end face of Pad24, origin (0, 0, 451), H (1, 0, 0), V (0, 1, 0)
    circle A1 centre (0, 0) radius 146.9733
  Fillet7: radius 10, on edge [start face of Pad24 | face of Pad24 from Sketch73.A1]
  Sketch77 on end face of Pad24, origin (0, 0, 451), H (1, 0, 0), V (0, 1, 0)
    circle A1 centre (0, 0) radius 33.214
    circle A2 centre (-50, 40) radius 5
    circle A3 centre (50, 40) radius 5
    circle A4 centre (-50, -40) radius 5
    circle A5 centre (50, -40) radius 5
    radius A2 = 5
    radius A3 = 5
    radius A5 = 5
    radius A4 = 5
  Pad25: profile Sketch76, direction (0, 0, 1), length 13
  Pad26: profile Sketch75, direction (0, 0, 1), length 13
  Pad27: profile Sketch74, direction (0, 0, 1), length 13
Body26, material "Satin light red"
  Pad28: profile Sketch77, direction (0, 0, 1), length 150
  Sketch78 on end face of Pad28, origin (0, 0, 601), H (1, 0, 0), V (0, 1, 0)
    construction line L1 (0, 82.4621) -> (0, -100)
    construction circle A1 centre (0, 0) radius 82.4621
    axis line L2 (0, 82.4621) -> (0, -82.4621)
    point P2 (0, 82.4621)
    point P3 (0, -82.4621)
    arc A2 centre (0, 0) radius 82.4621 from (0, 82.4621) to (0, -82.4621) ccw
    point P4 (76.8115, -30)
    line L3 (0, 82.4621) -> (0, -82.4621)
    point P5 (0, -82.4621)
    point P6 (0, 82.4621)
    vertical: L1 V, L2 V, L3 V
    coincidence: P2 A1, P3 A1, A2 P4, P4 A1, L1 P5, L1 P6, P2 P6, P3 P5
  Body27
    Shaft2: profile Sketch78, axis Sketch78.L3, angle 180
    Plane74: type 1Curve, Element1 edge [start face of Pad28 | face of Pad28 from Sketch77.A1]
    Plane75: type Offset, RefPlane Plane74, Offset 200
    Sketch79 on Plane75, origin (0, 0, 651), H (1, 0, 0), V (0, 1, 0)
      construction circle A1 centre (0, 0) radius 41.2311
    Sketch80 on Plane75, origin (0, 0, 651), H (1, 0, 0), V (0, 1, 0)
      construction circle A1 centre (0, 0) radius 44.7214
      point P1 (0, 44.7214)
      point P2 (43.589, -10)
      arc A2 centre (0, 0) radius 44.7214 from (0, 44.7214) to (0, -44.7214) ccw
      point P3 (40, -20)
      line L1 (0, 44.7214) -> (0, -44.7214)
      point P4 (0, -44.7214)
      coincidence: P1 A1, P1 V, P2 A1, A2 P3, P3 A1, P4 A1
      vertical: L1 V
    Body28
      Pad29: profile Sketch82, direction (0, 0, 1), length 35
    Remove3: tool Body28
    Sketch81 on Plane75, origin (0, 0, 651), H (1, 0, 0), V (0, 1, 0)
      point P1 (42.2568, -14.6786)
      construction circle A1 centre (0, 0) radius 44.7336
      point P2 (44.7336, 0)
      point P3 (0, 44.7336)
      point P4 (0, -44.7336)
      arc A2 centre (0, 0) radius 44.7336 from (0, 44.7336) to (0, -44.7336) ccw
      line L1 (0, 44.7336) -> (0, -44.7336)
      coincidence: A1 P1, A1 P2, P2 H, P3 A1, P3 V, P4 A1, A2 P1
      vertical: L1 V
    Shaft3: profile Sketch81, axis Sketch81.L1, angle 180
    Fillet8: radius 20, on edge [face of Shaft2 from Sketch78.A2 | start face of Pad29]
  Assemble2: tool Body27
Body29
  Sketch82 on Plane75, origin (0, 0, 651), H (1, 0, 0), V (0, 1, 0)
    line L1 (90, 90) -> (90, -90)
    line L2 (90, -90) -> (-90, -90)
    line L3 (-90, -90) -> (-90, 90)
    line L4 (-90, 90) -> (90, 90)
    vertical: L1 V, L3 V
    horizontal: L2 H, L4 H
    equidistance: L1 L3 O, L2 L4 O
